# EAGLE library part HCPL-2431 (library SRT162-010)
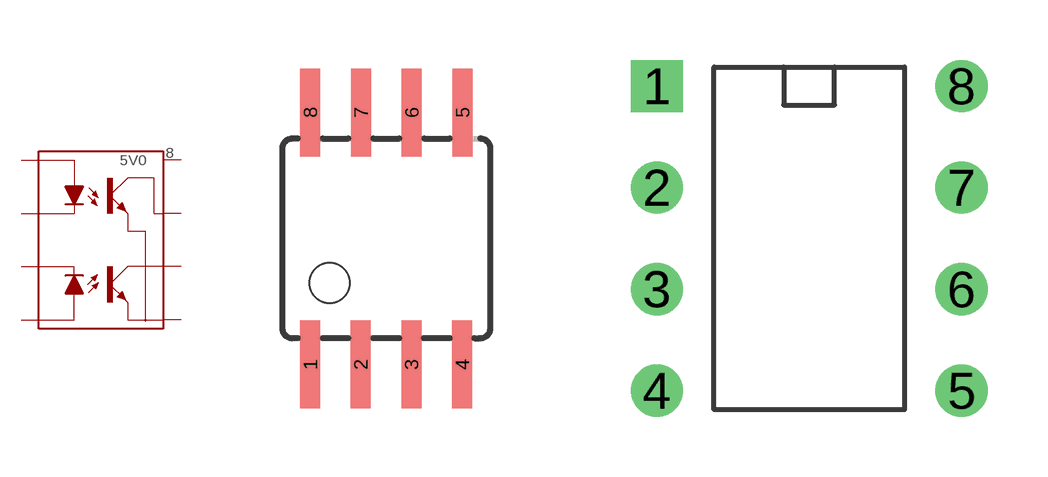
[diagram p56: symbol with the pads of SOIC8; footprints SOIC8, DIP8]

Designator prefix U

## HCPL-2431  [SOIC8]
1  VF1+  pas
2  VF1-  pas
3  VF2-  pas
4  VF2+  pas
5  GND  pwr
6  F2  pas
7  F1  pas
8  5V0  pwr

## HCPL-2431DIP  [DIP8]
Pads as for SOIC8

## Footprint SOIC8 (pad centres in mm)
smd 0.5 x 2.2: 1 -1.905,-3.154; 2 -0.645,-3.154; 3 0.625,-3.154; 4 1.895,-3.154; 5 1.905,3.154; 6 0.635,3.154; 7 -0.635,3.154; 8 -1.905,3.154

## Footprint DIP8 (pad centres in mm)
drill 0.8 square: 1 -3.81,3.81
drill 0.8 round: 2 -3.81,1.27; 3 -3.81,-1.27; 4 -3.81,-3.81; 5 3.81,-3.81; 6 3.81,-1.27; 7 3.81,1.27; 8 3.81,3.81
